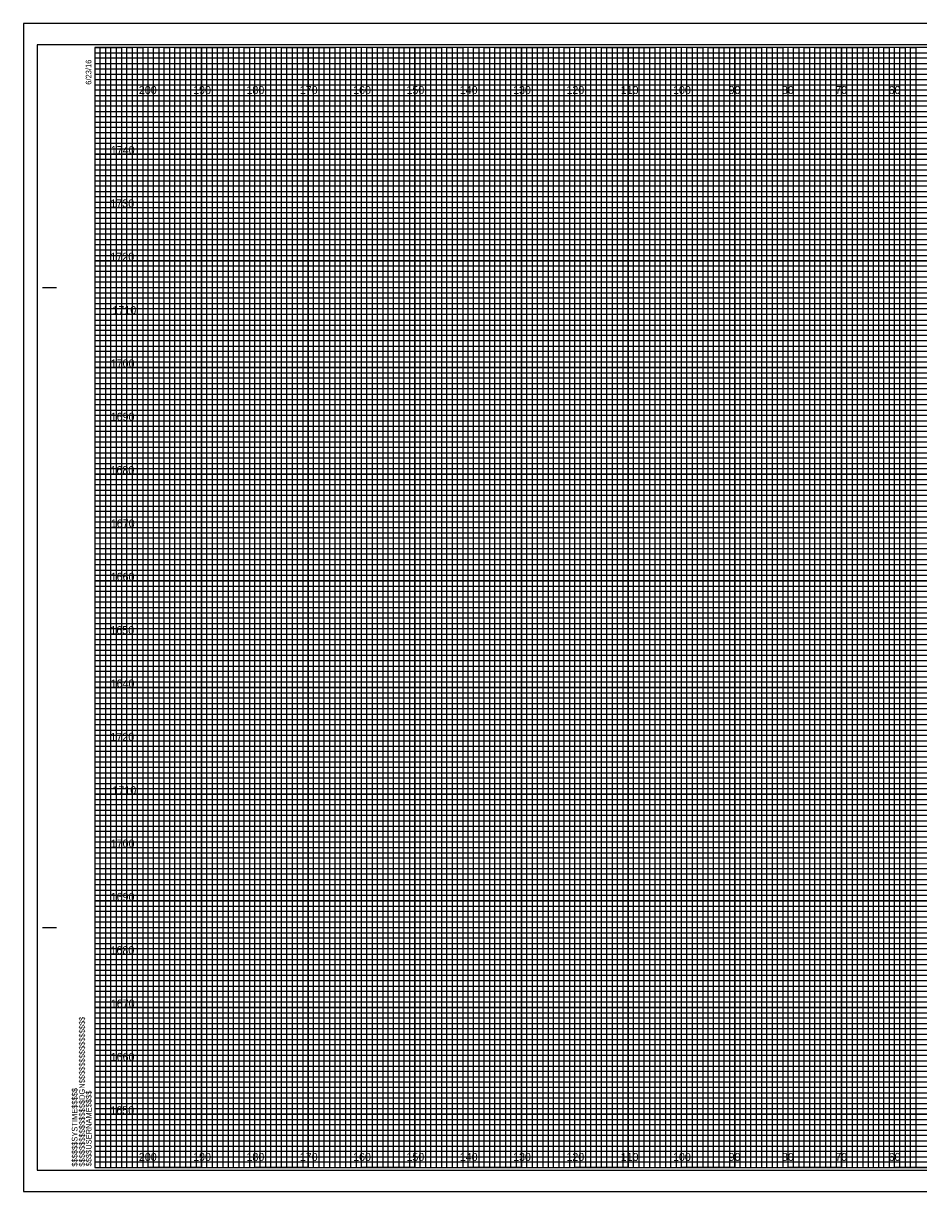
# Model space of a CAD drawing. Extents: x -3334 to 0, y 84 to 12624.
# Drawn here: x -711.6 to -543.7, y 304.2 to 523.2 of the extents above; entities that cross this region are included whole.
import ezdxf

# ---------------------------------------------------------------- set-up
doc = ezdxf.new("R2010")
doc.units = 0
for name, color, linetype in [('Old_Level_62', 7, 'Continuous'), ('Pattern 1', 7, 'Continuous'), ('Pattern 18', 7, 'Continuous'), ('Pattern 4', 7, 'Continuous'), ('Pattern 5', 7, 'Continuous'), ('Prop Dimension', 7, 'Continuous'), ('Prop Horizontal Alignment', 7, 'Continuous'), ('Raster_Level_0', 7, 'Continuous'), ('Scratch_Level_0', 7, 'Continuous'), ('Scratch_Level_3', 7, 'Continuous'), ('Scratch_Level_5', 7, 'Continuous')]:
    doc.layers.add(name, color=color, linetype=linetype)

msp = doc.modelspace()

# ---------------------------------------------------------------- linework, layer by layer
at = {"layer": 'Old_Level_62'}
for p, q in [((-708.04, 473.74), (-705.54, 473.74)), ((-707.94, 473.74), (-705.44, 473.74)), ((-708.04, 353.74), (-705.54, 353.74)), ((-707.94, 353.74), (-705.44, 353.74)), ((-698.24, 308.74), (-698.24, 308.74)), ((-698.24, 308.74), (-698.24, 308.74)), ((-698.24, 308.74), (-698.24, 308.74)), ((-698.24, 308.74), (-698.24, 308.74)), ((-698.24, 308.74), (-698.24, 308.74)), ((-698.24, 308.74), (-698.24, 308.74)), ((-698.24, 308.74), (-698.24, 308.74))]:
    msp.add_line(p, q, dxfattribs=at)
msp.add_lwpolyline([(-378.24, 518.74), (-698.24, 518.74), (-698.24, 308.74), (-378.24, 308.74)], close=True, dxfattribs=at)
at = {"layer": 'Pattern 18'}
msp.add_lwpolyline([(-711.64, 304.24), (-374.94, 304.24), (-374.94, 523.24), (-711.64, 523.24)], close=True, dxfattribs=at)
at = {"layer": 'Pattern 4'}
for p, q in [((-698.24, 517.74), (-438.24, 517.74)), ((-438.24, 516.72), (-698.24, 516.72)), ((-698.24, 516.72), (-698.24, 515.74)), ((-698.24, 515.74), (-438.24, 515.74)), ((-438.24, 514.63), (-698.24, 514.63)), ((-698.24, 514.63), (-698.24, 512.74)), ((-698.24, 512.74), (-378.24, 512.74))]:
    msp.add_line(p, q, dxfattribs=at)
for points in [[(-698.24, 511.74), (-428.24, 511.74), (-378.24, 511.74), (-378.24, 510.74), (-698.24, 510.74)], [(-698.24, 509.74), (-378.24, 509.74), (-378.24, 507.74), (-698.24, 507.74)], [(-698.24, 506.74), (-378.24, 506.74), (-378.24, 505.74), (-698.24, 505.72)], [(-698.24, 504.74), (-378.24, 504.74), (-378.24, 502.74), (-698.24, 502.74)], [(-698.24, 501.74), (-378.24, 501.74), (-378.24, 500.74), (-698.24, 500.74)], [(-698.24, 499.74), (-378.24, 499.74), (-378.24, 497.74), (-698.24, 497.74)], [(-698.24, 496.74), (-378.24, 496.74), (-378.24, 495.74), (-698.24, 495.74)], [(-698.24, 494.74), (-378.24, 494.74), (-378.24, 492.74), (-698.24, 492.74)], [(-698.24, 491.74), (-378.24, 491.74), (-378.24, 490.74), (-698.24, 490.74)], [(-698.24, 489.74), (-378.24, 489.74), (-378.24, 487.74), (-698.24, 487.74)], [(-698.24, 486.74), (-378.24, 486.74), (-378.24, 485.74), (-698.24, 485.74)], [(-698.24, 484.74), (-378.24, 484.74), (-378.24, 482.69), (-378.24, 481.74), (-378.24, 480.74), (-698.24, 480.74)], [(-698.24, 482.74), (-378.24, 482.74), (-378.24, 481.74), (-698.24, 481.74)], [(-698.24, 479.74), (-378.24, 479.74), (-378.24, 477.74), (-698.24, 477.77)], [(-698.24, 477.77), (-378.24, 477.74), (-378.24, 476.74), (-698.24, 476.74)], [(-698.24, 475.74), (-378.24, 475.74), (-378.24, 474.74), (-698.24, 474.74)], [(-698.24, 472.74), (-378.24, 472.74), (-378.24, 471.74), (-698.24, 471.74)], [(-698.24, 470.74), (-378.24, 470.74), (-378.24, 469.74), (-698.24, 469.74)], [(-698.31, 467.63), (-378.24, 467.63), (-378.24, 466.62), (-698.31, 466.62)], [(-698.24, 465.74), (-378.24, 465.74), (-378.24, 464.74), (-698.24, 464.74)], [(-698.24, 462.74), (-378.24, 462.74), (-378.24, 461.74), (-698.24, 461.74)], [(-698.24, 460.74), (-378.24, 460.74), (-378.24, 459.74), (-698.24, 459.74)], [(-698.24, 457.74), (-378.24, 457.74), (-378.24, 456.74), (-698.24, 456.74)], [(-698.24, 455.74), (-378.24, 455.74), (-378.24, 454.74), (-698.24, 454.74)], [(-698.24, 452.74), (-378.24, 452.74), (-378.24, 451.74), (-698.24, 451.74)], [(-698.24, 450.74), (-378.24, 450.74), (-378.24, 449.74), (-698.24, 449.74)], [(-698.24, 447.74), (-378.24, 447.74), (-378.25, 446.72), (-698.24, 446.74)], [(-698.24, 445.74), (-378.24, 445.74), (-378.24, 444.74), (-698.24, 444.74)], [(-698.24, 442.74), (-378.24, 442.74), (-378.24, 441.74), (-698.24, 441.74)], [(-698.24, 440.74), (-378.24, 440.74), (-378.24, 439.74), (-698.24, 439.74)], [(-698.24, 437.74), (-378.24, 437.74), (-378.24, 436.74), (-698.24, 436.74)], [(-698.24, 435.74), (-378.24, 435.74), (-378.24, 434.74), (-698.24, 434.74)], [(-698.24, 432.74), (-378.24, 432.74), (-378.24, 431.74), (-698.24, 431.74)], [(-698.24, 430.74), (-378.24, 430.74), (-378.24, 429.74), (-698.24, 429.74)], [(-698.24, 427.74), (-378.24, 427.74), (-378.24, 426.74), (-698.24, 426.74)], [(-698.24, 425.73), (-378.17, 425.65), (-378.24, 424.74), (-698.24, 424.74)], [(-698.24, 422.74), (-378.24, 422.74), (-378.24, 421.74), (-698.24, 421.74)], [(-698.24, 420.74), (-378.24, 420.74), (-378.24, 419.74), (-698.24, 419.74)], [(-698.24, 417.74), (-378.24, 417.74), (-378.24, 416.74), (-698.24, 416.74)], [(-698.24, 415.74), (-378.24, 415.74), (-378.24, 414.74), (-698.24, 414.74)], [(-698.24, 412.74), (-378.24, 412.74), (-378.24, 411.74), (-698.24, 411.74)], [(-698.24, 410.74), (-378.24, 410.74), (-378.24, 409.74), (-698.24, 409.74)], [(-698.24, 407.74), (-378.24, 407.74), (-378.24, 406.74), (-698.24, 406.74)], [(-698.24, 405.74), (-378.24, 405.74), (-378.24, 404.74), (-698.24, 404.74)], [(-698.24, 402.74), (-378.24, 402.74), (-378.24, 401.74), (-698.24, 401.74)], [(-698.24, 400.74), (-378.24, 400.74), (-378.24, 399.74), (-698.24, 399.74)], [(-698.24, 397.74), (-378.24, 397.74), (-378.24, 396.74), (-698.24, 396.74)], [(-698.24, 395.74), (-378.24, 395.74), (-378.24, 394.74), (-698.24, 394.74)], [(-698.24, 392.74), (-378.24, 392.74), (-378.24, 391.74), (-698.24, 391.74)], [(-698.24, 390.74), (-378.24, 390.74), (-378.24, 389.74), (-698.24, 389.74)], [(-698.24, 387.74), (-378.24, 387.74), (-378.25, 386.72), (-698.24, 386.74)], [(-698.24, 385.74), (-378.24, 385.74), (-378.24, 384.74), (-698.24, 384.74)], [(-698.24, 382.74), (-378.24, 382.74), (-378.24, 381.74), (-698.24, 381.74)], [(-698.24, 380.74), (-378.24, 380.74), (-378.24, 379.74), (-698.24, 379.74)], [(-698.24, 377.74), (-378.24, 377.74), (-378.24, 376.74), (-698.24, 376.74)], [(-698.24, 375.74), (-378.24, 375.74), (-378.24, 374.74), (-698.24, 374.74)], [(-698.24, 372.74), (-378.24, 372.74), (-378.24, 371.74), (-698.24, 371.74)], [(-698.24, 370.74), (-378.24, 370.74), (-378.24, 369.74), (-698.24, 369.74)], [(-698.24, 367.74), (-378.24, 367.74), (-378.24, 366.74), (-698.24, 366.74)], [(-698.24, 365.73), (-378.17, 365.65), (-378.24, 364.74), (-698.24, 364.74)], [(-698.24, 362.74), (-378.24, 362.74), (-378.24, 361.74), (-698.24, 361.74)], [(-698.24, 360.74), (-378.24, 360.74), (-378.24, 359.74), (-698.24, 359.74)], [(-698.24, 357.74), (-378.24, 357.74), (-378.24, 356.74), (-698.24, 356.74)], [(-698.24, 355.74), (-378.24, 355.74), (-378.24, 354.74), (-698.24, 354.74)], [(-698.24, 352.74), (-378.24, 352.74), (-378.24, 351.74), (-698.24, 351.74)], [(-698.24, 350.74), (-378.24, 350.74), (-378.24, 349.74), (-698.24, 349.74)], [(-698.24, 347.74), (-378.24, 347.74), (-378.24, 346.74), (-698.24, 346.74)], [(-698.24, 345.74), (-378.24, 345.74), (-378.24, 344.74), (-698.24, 344.74)], [(-698.24, 342.74), (-378.24, 342.74), (-378.24, 341.74), (-698.24, 341.74)], [(-698.24, 340.74), (-378.24, 340.74), (-378.24, 339.74), (-698.24, 339.74)], [(-698.24, 337.74), (-378.24, 337.74), (-378.24, 336.74), (-698.24, 336.74)], [(-698.24, 335.74), (-378.24, 335.74), (-378.24, 334.74), (-698.24, 334.74)], [(-698.24, 332.74), (-378.24, 332.74), (-378.24, 331.74), (-698.24, 331.74)], [(-698.24, 330.74), (-378.24, 330.74), (-378.24, 329.74), (-698.24, 329.74)], [(-698.24, 327.74), (-378.24, 327.74), (-378.24, 326.74), (-698.24, 326.74)], [(-698.24, 325.74), (-378.24, 325.74), (-378.24, 324.74), (-698.24, 324.74)], [(-698.24, 322.74), (-378.24, 322.74), (-378.24, 321.74), (-698.24, 321.74)], [(-698.24, 320.74), (-378.24, 320.74), (-378.24, 319.74), (-698.24, 319.74)], [(-698.24, 317.74), (-378.24, 317.74), (-378.24, 316.74), (-698.24, 316.74)], [(-698.24, 315.74), (-378.24, 315.74), (-378.24, 314.74), (-698.24, 314.74)], [(-698.24, 312.74), (-378.24, 312.74), (-378.24, 311.74), (-698.24, 311.74)], [(-698.24, 310.74), (-378.24, 310.74), (-378.24, 309.74), (-698.24, 309.74)]]:
    msp.add_lwpolyline(points, dxfattribs=at)
at = {"layer": 'Pattern 5'}
for p, q in [((-374.94, 523.24), (-711.64, 523.24)), ((-711.64, 523.24), (-711.64, 304.24)), ((-711.64, 304.24), (-374.94, 304.24))]:
    msp.add_line(p, q, dxfattribs=at)
at = {"layer": 'Prop Dimension'}
for points in [[(-698.24, 308.74), (-697.24, 308.74), (-697.24, 518.74), (-696.24, 518.74), (-696.24, 308.74)], [(-696.24, 308.74), (-695.24, 308.74), (-695.24, 518.74), (-694.24, 518.74), (-694.24, 308.74)], [(-693.24, 308.74), (-692.24, 308.74), (-692.24, 518.74), (-691.24, 518.74), (-691.24, 308.74)], [(-691.24, 308.74), (-690.24, 308.74), (-690.24, 518.74), (-689.24, 518.74), (-689.24, 308.74)], [(-688.24, 308.74), (-687.24, 308.74), (-687.24, 518.74), (-686.24, 518.74), (-686.24, 308.74)], [(-686.24, 308.74), (-685.24, 308.74), (-685.24, 518.74), (-684.24, 518.74), (-684.24, 308.74)], [(-683.24, 308.74), (-682.24, 308.74), (-682.24, 518.74), (-681.24, 518.74), (-681.24, 308.74)], [(-681.24, 308.74), (-680.24, 308.74), (-680.24, 518.74), (-679.24, 518.74), (-679.24, 308.74)], [(-678.24, 308.74), (-677.24, 308.74), (-677.24, 518.74), (-676.24, 518.74), (-676.24, 308.74)], [(-676.24, 308.74), (-675.24, 308.74), (-675.24, 518.74), (-674.24, 518.74), (-674.24, 308.74)], [(-673.24, 308.74), (-672.24, 308.74), (-672.24, 518.74), (-671.24, 518.74), (-671.24, 308.74)], [(-671.24, 308.74), (-670.24, 308.74), (-670.24, 518.74), (-669.24, 518.74), (-669.24, 308.74)], [(-668.24, 308.74), (-667.24, 308.74), (-667.24, 518.74), (-666.24, 518.74), (-666.24, 308.74)], [(-666.24, 308.74), (-665.24, 308.74), (-665.24, 518.74), (-664.24, 518.74), (-664.24, 308.74)], [(-663.24, 308.74), (-662.24, 308.74), (-662.24, 518.74), (-661.24, 518.74), (-661.24, 308.74)], [(-661.24, 308.74), (-660.24, 308.74), (-660.24, 518.74), (-659.24, 518.74), (-659.24, 308.74)], [(-658.24, 308.74), (-657.24, 308.74), (-657.24, 518.74), (-656.24, 518.74), (-656.24, 308.74)], [(-656.24, 308.74), (-655.24, 308.74), (-655.24, 518.74), (-654.24, 518.74), (-654.24, 308.74)], [(-653.24, 308.74), (-652.24, 308.74), (-652.24, 518.74), (-651.24, 518.74), (-651.24, 308.74)], [(-651.24, 308.74), (-650.24, 308.74), (-650.24, 518.74), (-649.24, 518.74), (-649.24, 308.74)], [(-648.24, 308.74), (-647.24, 308.74), (-647.24, 518.74), (-646.24, 518.74), (-646.24, 308.74)], [(-646.24, 308.74), (-645.24, 308.74), (-645.24, 518.74), (-644.24, 518.74), (-644.24, 308.74)], [(-643.24, 308.74), (-642.24, 308.74), (-642.24, 518.74), (-641.24, 518.74), (-641.24, 308.74)], [(-641.24, 308.74), (-640.24, 308.74), (-640.24, 518.74), (-639.24, 518.74), (-639.24, 308.74)], [(-638.24, 308.74), (-637.24, 308.74), (-637.24, 518.74), (-636.24, 518.74), (-636.24, 308.74)], [(-636.24, 308.74), (-635.24, 308.74), (-635.24, 518.74), (-634.24, 518.74), (-634.24, 308.74)], [(-633.24, 308.74), (-632.24, 308.74), (-632.24, 518.74), (-631.24, 518.74), (-631.24, 308.74)], [(-631.24, 308.74), (-630.24, 308.74), (-630.24, 518.74), (-629.24, 518.74), (-629.24, 308.74)], [(-628.24, 308.74), (-627.24, 308.74), (-627.24, 518.74), (-626.24, 518.74), (-626.24, 308.74)], [(-626.24, 308.74), (-625.24, 308.74), (-625.24, 518.74), (-624.24, 518.74), (-624.24, 308.74)], [(-623.24, 308.74), (-622.24, 308.74), (-622.24, 518.74), (-621.24, 518.74), (-621.24, 308.74)], [(-621.24, 308.74), (-620.24, 308.74), (-620.24, 518.74), (-619.24, 518.74), (-619.24, 308.74)], [(-618.24, 308.74), (-617.24, 308.74), (-617.24, 518.74), (-616.24, 518.74), (-616.24, 308.74)], [(-616.24, 308.74), (-615.24, 308.74), (-615.24, 518.74), (-614.24, 518.74), (-614.24, 308.74)], [(-613.24, 308.74), (-612.24, 308.74), (-612.24, 518.74), (-611.24, 518.74), (-611.24, 308.74)], [(-611.24, 308.74), (-610.24, 308.74), (-610.24, 518.74), (-609.24, 518.74), (-609.24, 308.74)], [(-608.24, 308.74), (-607.24, 308.74), (-607.24, 518.74), (-606.24, 518.74), (-606.24, 308.74)], [(-606.24, 308.74), (-605.24, 308.74), (-605.24, 518.74), (-604.24, 518.74), (-604.24, 308.74)], [(-603.24, 308.74), (-602.24, 308.74), (-602.24, 518.74), (-601.24, 518.74), (-601.24, 308.74)], [(-601.24, 308.74), (-600.24, 308.74), (-600.24, 518.74), (-599.24, 518.74), (-599.24, 308.74)], [(-598.24, 308.74), (-597.24, 308.74), (-597.24, 518.74), (-596.24, 518.74), (-596.24, 308.74)], [(-596.24, 308.74), (-595.24, 308.74), (-595.24, 518.74), (-594.24, 518.74), (-594.24, 308.74)], [(-593.24, 308.74), (-592.24, 308.74), (-592.24, 518.74), (-591.24, 518.74), (-591.24, 308.74)], [(-591.24, 308.74), (-590.24, 308.74), (-590.24, 518.74), (-589.24, 518.74), (-589.24, 308.74)], [(-588.24, 308.74), (-587.24, 308.74), (-587.24, 518.74), (-586.24, 518.74), (-586.24, 308.74)], [(-586.24, 308.74), (-585.24, 308.74), (-585.24, 518.74), (-584.24, 518.74), (-584.24, 308.74)], [(-583.24, 308.74), (-582.24, 308.74), (-582.24, 518.74), (-581.24, 518.74), (-581.24, 308.74)], [(-581.24, 308.74), (-580.24, 308.74), (-580.24, 518.74), (-579.24, 518.74), (-579.24, 308.74)], [(-578.24, 308.74), (-577.24, 308.74), (-577.24, 518.74), (-576.24, 518.74), (-576.24, 308.74)], [(-576.24, 308.74), (-575.24, 308.74), (-575.24, 518.74), (-574.24, 518.74), (-574.24, 308.74)], [(-573.24, 308.74), (-572.24, 308.74), (-572.24, 518.74), (-571.24, 518.74), (-571.24, 308.74)], [(-571.24, 308.74), (-570.24, 308.74), (-570.24, 518.74), (-569.24, 518.74), (-569.24, 308.74)], [(-568.24, 308.74), (-567.24, 308.74), (-567.24, 518.74), (-566.24, 518.74), (-566.24, 308.74)], [(-566.24, 308.74), (-565.24, 308.74), (-565.24, 518.74), (-564.24, 518.74), (-564.24, 308.74)], [(-563.24, 308.74), (-562.24, 308.74), (-562.24, 518.74), (-561.24, 518.74), (-561.24, 308.74)], [(-561.24, 308.74), (-560.24, 308.74), (-560.24, 518.74), (-559.24, 518.74), (-559.24, 308.74)], [(-558.24, 308.74), (-557.24, 308.74), (-557.24, 518.74), (-556.24, 518.74), (-556.24, 308.74)], [(-556.24, 308.74), (-555.24, 308.74), (-555.24, 518.74), (-554.24, 518.74), (-554.24, 308.74)], [(-553.24, 308.74), (-552.24, 308.74), (-552.24, 518.74), (-551.24, 518.74), (-551.24, 308.74)], [(-551.24, 308.74), (-550.24, 308.74), (-550.24, 518.74), (-549.24, 518.74), (-549.24, 308.74)], [(-548.24, 308.74), (-547.24, 308.74), (-547.24, 518.74), (-546.24, 518.74), (-546.24, 308.74)], [(-546.24, 308.74), (-545.24, 308.74), (-545.24, 518.74), (-544.24, 518.74), (-544.24, 308.74)]]:
    msp.add_lwpolyline(points, dxfattribs=at)
at = {"layer": 'Prop Horizontal Alignment'}
for points in [[(-698.24, 518.74), (-693.24, 518.74), (-693.24, 308.74), (-683.24, 308.74), (-683.24, 518.74), (-673.24, 518.74), (-673.24, 308.74), (-663.24, 308.74), (-663.24, 518.74), (-653.24, 518.74), (-653.24, 308.74), (-643.24, 308.74), (-643.24, 518.74), (-633.24, 518.74), (-633.24, 308.74), (-623.24, 308.74), (-623.24, 518.74), (-613.24, 518.74), (-613.24, 308.74), (-603.24, 308.74), (-603.24, 518.74), (-593.24, 518.74), (-593.24, 308.74), (-583.24, 308.74), (-583.24, 518.74), (-573.24, 518.74), (-573.24, 308.74), (-563.24, 308.74), (-563.24, 518.74), (-553.24, 518.74), (-553.24, 308.74), (-543.24, 308.74)], [(-698.24, 513.74), (-423.24, 513.74)], [(-698.24, 493.74), (-378.24, 493.74), (-378.24, 503.74), (-698.24, 503.74)], [(-698.24, 473.74), (-378.24, 473.74), (-378.24, 483.74), (-698.24, 483.74)], [(-698.24, 453.74), (-378.24, 453.74), (-378.24, 463.74), (-698.24, 463.74)], [(-698.24, 433.74), (-378.24, 433.74), (-378.24, 443.74), (-698.24, 443.74)], [(-698.24, 413.74), (-378.24, 413.74), (-378.24, 423.74), (-698.24, 423.74)], [(-698.24, 393.74), (-378.24, 393.74), (-378.24, 403.74), (-698.24, 403.74)], [(-698.24, 373.74), (-378.24, 373.74), (-378.24, 383.74), (-698.24, 383.74)], [(-698.24, 353.74), (-378.24, 353.74), (-378.24, 363.74), (-698.24, 363.74)], [(-698.24, 333.74), (-378.24, 333.74), (-378.24, 343.74), (-698.24, 343.74)], [(-698.24, 313.74), (-378.24, 313.74), (-378.24, 323.74), (-698.24, 323.74)]]:
    msp.add_lwpolyline(points, dxfattribs=at)
at = {"layer": 'Scratch_Level_0'}
for p, q in [((-688.24, 308.74), (-688.24, 518.74)), ((-678.24, 308.74), (-678.24, 518.74)), ((-668.24, 308.74), (-668.24, 518.74)), ((-658.24, 308.74), (-658.24, 518.74)), ((-648.24, 308.74), (-648.24, 518.74)), ((-638.24, 308.74), (-638.24, 518.74)), ((-628.24, 308.74), (-628.24, 518.74)), ((-618.24, 308.74), (-618.24, 518.74)), ((-608.24, 308.74), (-608.24, 518.74)), ((-598.24, 308.74), (-598.24, 518.74)), ((-588.24, 308.74), (-588.24, 518.74)), ((-578.24, 308.74), (-578.24, 518.74)), ((-568.24, 308.74), (-568.24, 518.74)), ((-558.24, 308.74), (-558.24, 518.74)), ((-548.24, 308.74), (-548.24, 518.74)), ((-698.24, 508.74), (-378.24, 508.74)), ((-698.24, 498.74), (-378.24, 498.74)), ((-698.24, 488.74), (-378.24, 488.74)), ((-698.24, 478.74), (-378.24, 478.74)), ((-698.24, 468.74), (-378.24, 468.74)), ((-698.24, 458.74), (-378.24, 458.74)), ((-698.24, 448.74), (-378.24, 448.74)), ((-698.24, 438.74), (-378.24, 438.74)), ((-698.24, 428.74), (-378.24, 428.74)), ((-698.24, 418.74), (-378.24, 418.74)), ((-698.24, 408.74), (-378.24, 408.74)), ((-698.24, 398.74), (-378.24, 398.74)), ((-698.24, 388.74), (-378.24, 388.74)), ((-698.24, 378.74), (-378.24, 378.74)), ((-698.24, 368.74), (-378.24, 368.74)), ((-698.24, 358.74), (-378.24, 358.74)), ((-698.24, 348.74), (-378.24, 348.74)), ((-698.24, 338.74), (-378.24, 338.74)), ((-698.24, 328.74), (-378.24, 328.74)), ((-698.24, 318.74), (-378.24, 318.74))]:
    msp.add_line(p, q, dxfattribs=at)
at = {"layer": 'Scratch_Level_3'}
for p, q in [((-688.24, 518.74), (-698.24, 518.74)), ((-688.24, 308.74), (-688.24, 518.74)), ((-668.24, 518.74), (-678.24, 518.74)), ((-678.24, 518.74), (-678.24, 308.74)), ((-668.24, 308.74), (-668.24, 518.74)), ((-648.24, 518.74), (-658.24, 518.74)), ((-658.24, 518.74), (-658.24, 308.74)), ((-648.24, 308.74), (-648.24, 518.74)), ((-628.24, 518.74), (-638.24, 518.74)), ((-638.24, 518.74), (-638.24, 308.74)), ((-628.24, 308.74), (-628.24, 518.74)), ((-608.24, 518.74), (-618.24, 518.74)), ((-618.24, 518.74), (-618.24, 308.74)), ((-608.24, 308.74), (-608.24, 518.74)), ((-588.24, 518.74), (-598.24, 518.74)), ((-598.24, 518.74), (-598.24, 308.74)), ((-588.24, 308.74), (-588.24, 518.74)), ((-568.24, 518.74), (-578.24, 518.74)), ((-578.24, 518.74), (-578.24, 308.74)), ((-568.24, 308.74), (-568.24, 518.74)), ((-548.24, 518.74), (-558.24, 518.74)), ((-558.24, 518.74), (-558.24, 308.74)), ((-548.24, 308.74), (-548.24, 518.74)), ((-678.24, 308.74), (-688.24, 308.74)), ((-658.24, 308.74), (-668.24, 308.74)), ((-638.24, 308.74), (-648.24, 308.74)), ((-618.24, 308.74), (-628.24, 308.74)), ((-598.24, 308.74), (-608.24, 308.74)), ((-578.24, 308.74), (-588.24, 308.74)), ((-558.24, 308.74), (-568.24, 308.74)), ((-538.24, 308.74), (-548.24, 308.74))]:
    msp.add_line(p, q, dxfattribs=at)
for points in [[(-698.24, 508.74), (-378.24, 508.74), (-378.24, 498.74), (-698.24, 498.74)], [(-698.24, 488.74), (-378.24, 488.74), (-378.24, 478.74), (-698.24, 478.74)], [(-698.24, 468.74), (-378.24, 468.74), (-378.24, 458.74), (-698.24, 458.74)], [(-698.24, 448.74), (-378.24, 448.74), (-378.24, 438.74), (-698.24, 438.74)], [(-698.24, 428.74), (-378.24, 428.74), (-378.24, 418.74), (-698.24, 418.74)], [(-698.24, 408.74), (-378.24, 408.74), (-378.24, 398.74), (-698.24, 398.74)], [(-698.24, 388.74), (-378.24, 388.74), (-378.24, 378.74), (-698.24, 378.74)], [(-698.24, 368.74), (-378.24, 368.74), (-378.24, 358.74), (-698.24, 358.74)], [(-698.24, 348.74), (-378.24, 348.74), (-378.24, 338.74), (-698.24, 338.74)], [(-698.24, 328.74), (-378.24, 328.74), (-378.24, 318.74), (-698.24, 318.74)]]:
    msp.add_lwpolyline(points, dxfattribs=at)
at = {"layer": 'Scratch_Level_5'}
msp.add_lwpolyline([(-709.04, 308.24), (-375.84, 308.24), (-375.84, 519.24), (-709.04, 519.24)], close=True, dxfattribs=at)

# ---------------------------------------------------------------- texts
at = {"layer": 'Old_Level_62'}
for s, p in [('6/23/16', (-698.89, 511.74)), ('$$$$$$$$$$$$$$$$DGN$$$$$$$$$$$$$$$$', (-700.12, 308.92)), ('$$$$$$SYSTIME$$$$$', (-701.5, 308.92)), ('$$$$USERNAME$$$$', (-698.86, 308.97))]:
    msp.add_text(s, height=1.05, rotation=90, dxfattribs=at).set_placement(p)
at = {"layer": 'Pattern 1'}
for s, p in [('1740', (-695.24, 498.74)), ('1730', (-695.32, 488.74)), ('1720', (-695.31, 478.74)), ('1710', (-694.93, 468.74)), ('1700', (-695.26, 458.74)), ('1690', (-695.27, 448.74)), ('1680', (-695.3, 438.74)), ('1670', (-695.24, 428.74)), ('1660', (-695.27, 418.74)), ('1650', (-695.32, 408.74)), ('1640', (-695.27, 398.74)), ('1720', (-695.31, 388.74)), ('1710', (-694.93, 378.74)), ('1700', (-695.26, 368.74)), ('1690', (-695.27, 358.74)), ('1680', (-695.3, 348.74)), ('1670', (-695.24, 338.74)), ('1660', (-695.27, 328.74)), ('1650', (-695.32, 318.74))]:
    msp.add_text(s, height=1.5, dxfattribs=at).set_placement(p)
at = {"layer": 'Raster_Level_0'}
for s, p in [('200', (-689.98, 509.99)), ('190', (-679.8, 509.99)), ('180', (-669.8, 509.99)), ('170', (-659.8, 509.99)), ('160', (-649.8, 509.99)), ('150', (-639.8, 509.99)), ('140', (-629.8, 509.99)), ('130', (-619.8, 509.99)), ('120', (-609.8, 509.99)), ('110', (-599.62, 509.99)), ('100', (-589.8, 509.99)), ('90', (-579.38, 509.99)), ('80', (-569.38, 509.99)), ('70', (-559.38, 509.99)), ('60', (-549.38, 509.99)), ('200', (-689.98, 309.99)), ('190', (-679.8, 309.99)), ('180', (-669.8, 309.99)), ('170', (-659.8, 309.99)), ('160', (-649.8, 309.99)), ('150', (-639.8, 309.99)), ('140', (-629.8, 309.99)), ('130', (-619.8, 309.99)), ('120', (-609.8, 309.99)), ('110', (-599.62, 309.99)), ('100', (-589.8, 309.99)), ('90', (-579.38, 309.99)), ('80', (-569.38, 309.99)), ('70', (-559.38, 309.99)), ('60', (-549.38, 309.99))]:
    msp.add_text(s, height=1.5, dxfattribs=at).set_placement(p)

doc.saveas('drawing.dxf')
